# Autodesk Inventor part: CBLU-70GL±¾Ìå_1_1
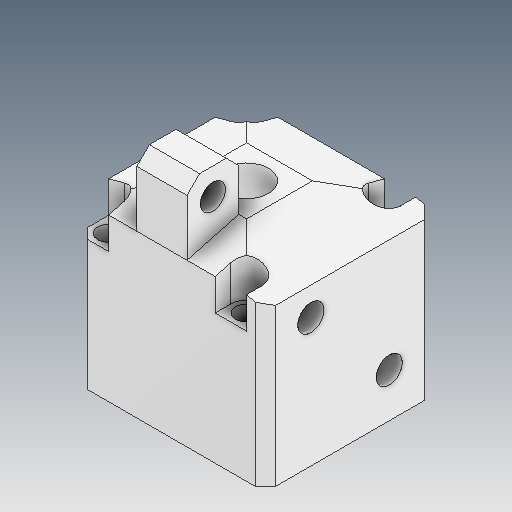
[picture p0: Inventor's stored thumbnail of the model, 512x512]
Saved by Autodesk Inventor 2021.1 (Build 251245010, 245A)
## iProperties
Created: 2021-05
Part Number: CBLU-70GL±¾Ìå_1_1
Material: Ogólny
Document SubType Name: Modeling
Designer: user
Density: 1 g/cm^3
Appearance: Domyślna
Author: user
Revision Number: ÈÎºÎ
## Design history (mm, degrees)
feature "ÊäÈë1"
feature "ÊäÈë2"
node "Bryła1"
node "Bryła2"
